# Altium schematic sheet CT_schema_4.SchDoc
size 461 x 312 mm
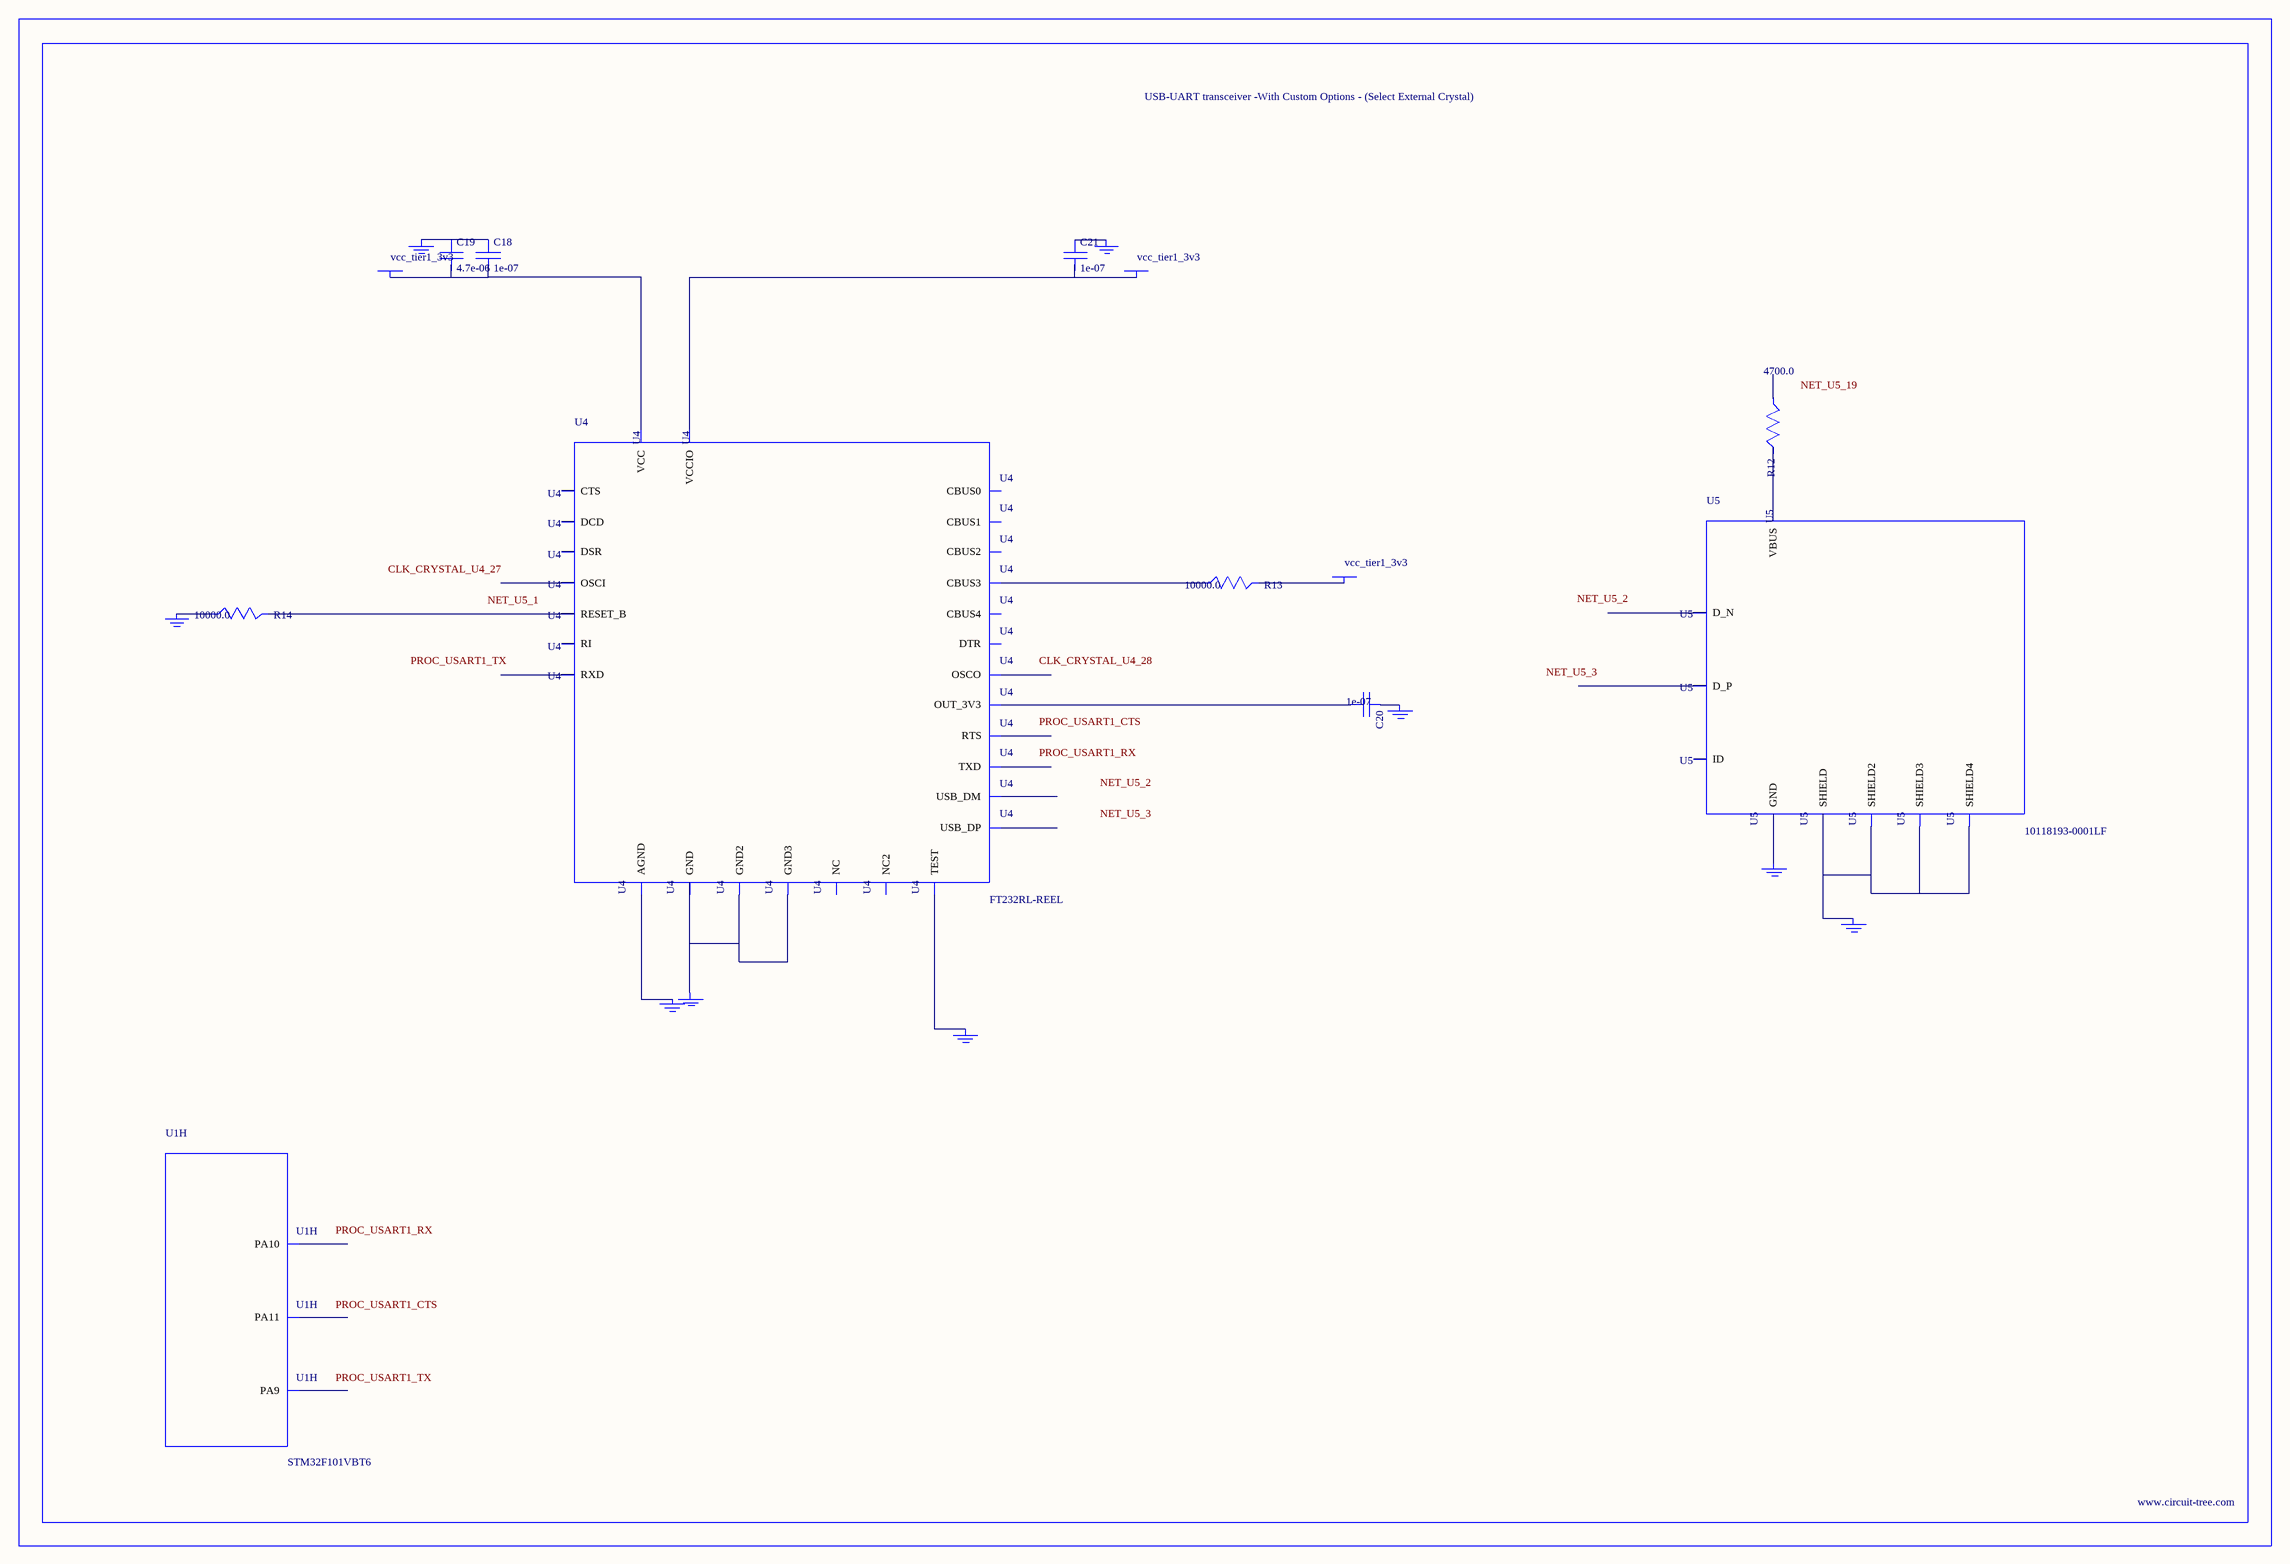
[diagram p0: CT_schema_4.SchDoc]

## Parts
BORDER3  (no value)
C18  1e-07  [C0402]
C19  4.7e-06  [C0805]
C20  1e-07  [C0402]
C21  1e-07  [C0402]
GND_INSTANCE_3_0  (no value)
GND_INSTANCE_3_1  (no value)
GND_INSTANCE_3_2  (no value)
GND_INSTANCE_3_3  (no value)
GND_INSTANCE_3_4  (no value)
GND_INSTANCE_3_5  (no value)
GND_INSTANCE_3_6  (no value)
GND_INSTANCE_3_7  (no value)
GND_INSTANCE_3_8  (no value)
POWER_INSTANCE_3_0  vcc_tier1_3v3
POWER_INSTANCE_3_1  vcc_tier1_3v3
POWER_INSTANCE_3_2  vcc_tier1_3v3
R12  4700.0  [R0603]
R13  10000.0  [R0603]
R14  10000.0  [R0603]
U1  STM32F101VBT6  [LQFP100]  (part H of 9)
U4  FT232RL-REEL  [SSOP-28]
U5  10118193-0001LF  [FCI_10118193-0001LF]

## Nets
NetC18_1: C18.1 C19.1 GND_INSTANCE_3_3.0(GND)
NetC18_2: C18.2 C19.2 POWER_INSTANCE_3_2.0(PWR) U4.20(VCC)
NetC20_1: C20.1 GND_INSTANCE_3_1.0(GND)
NetC20_2: C20.2 U4.17(OUT_3V3)
NetC21_1: C21.1 GND_INSTANCE_3_0.0(GND)
NetC21_2: C21.2 POWER_INSTANCE_3_0.0(PWR) U4.4(VCCIO)
NetGND_INSTANCE_3_2_0: GND_INSTANCE_3_2.0(GND) R14.1
NetGND_INSTANCE_3_4_0: GND_INSTANCE_3_4.0(GND) U4.25(AGND)
NetGND_INSTANCE_3_5_0: GND_INSTANCE_3_5.0(GND) U4.26(TEST)
NetGND_INSTANCE_3_6_0: GND_INSTANCE_3_6.0(GND) U4.7(GND) U4.18(GND2) U4.21(GND3)
NetGND_INSTANCE_3_7_0: GND_INSTANCE_3_7.0(GND) U5.6(SHIELD) U5.7(SHIELD2) U5.8(SHIELD3) U5.9(SHIELD4)
NetGND_INSTANCE_3_8_0: GND_INSTANCE_3_8.0(GND) U5.5(GND)
NetPOWER_INSTANCE_3_1_0: POWER_INSTANCE_3_1.0(PWR) R13.2
NetR12_2: R12.2 U5.1(VBUS)
NetR13_1: R13.1 U4.14(CBUS3)
NetR14_2: R14.2 U4.19(RESET_B)

Not connected (* = marked no-connect by the designer): R12 1; U1 68(PA9) 69(PA10) 70(PA11); U4 1(TXD) 2(DTR) 3(RTS) 5(RXD) 6(RI) 8(NC) 9(DSR) 10(DCD) 11(CTS) 12(CBUS4) 13(CBUS2) 15(USB_DP) 16(USB_DM) 22(CBUS1) 23(CBUS0) 24(NC2) 27(OSCI) 28(OSCO); U5 2(D_N) 3(D_P) 4(ID)

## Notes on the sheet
- Labels drawn without touching a wire or pin: CLK_CRYSTAL_U4_27, CLK_CRYSTAL_U4_28, NET_U5_1, NET_U5_2, NET_U5_3, NET_U5_19, PROC_USART1_CTS, PROC_USART1_RX, PROC_USART1_TX

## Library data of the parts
BORDER3 = BORDER_PAGE3
C18 C20 C21 = C0402C104K3RACTU
C19 = C0805C475K4RACTU
GND_INSTANCE_3_0-GND_INSTANCE_3_8 = GND
POWER_INSTANCE_3_0-POWER_INSTANCE_3_2 = PWR
R12 = RC0603JR-074K7L
R13 R14 = RC0603JR-0710KL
